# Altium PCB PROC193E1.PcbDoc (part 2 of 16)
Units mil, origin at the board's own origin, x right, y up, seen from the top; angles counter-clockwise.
Board outline 7700 x 2300 mil, 6 copper layers (Top Layer, GND 1, SIG 1, PWR, GND 2, Bottom Layer), stack 60.98 mil thick; 946 components, 667 nets, 9401 pads, 1730 vias.
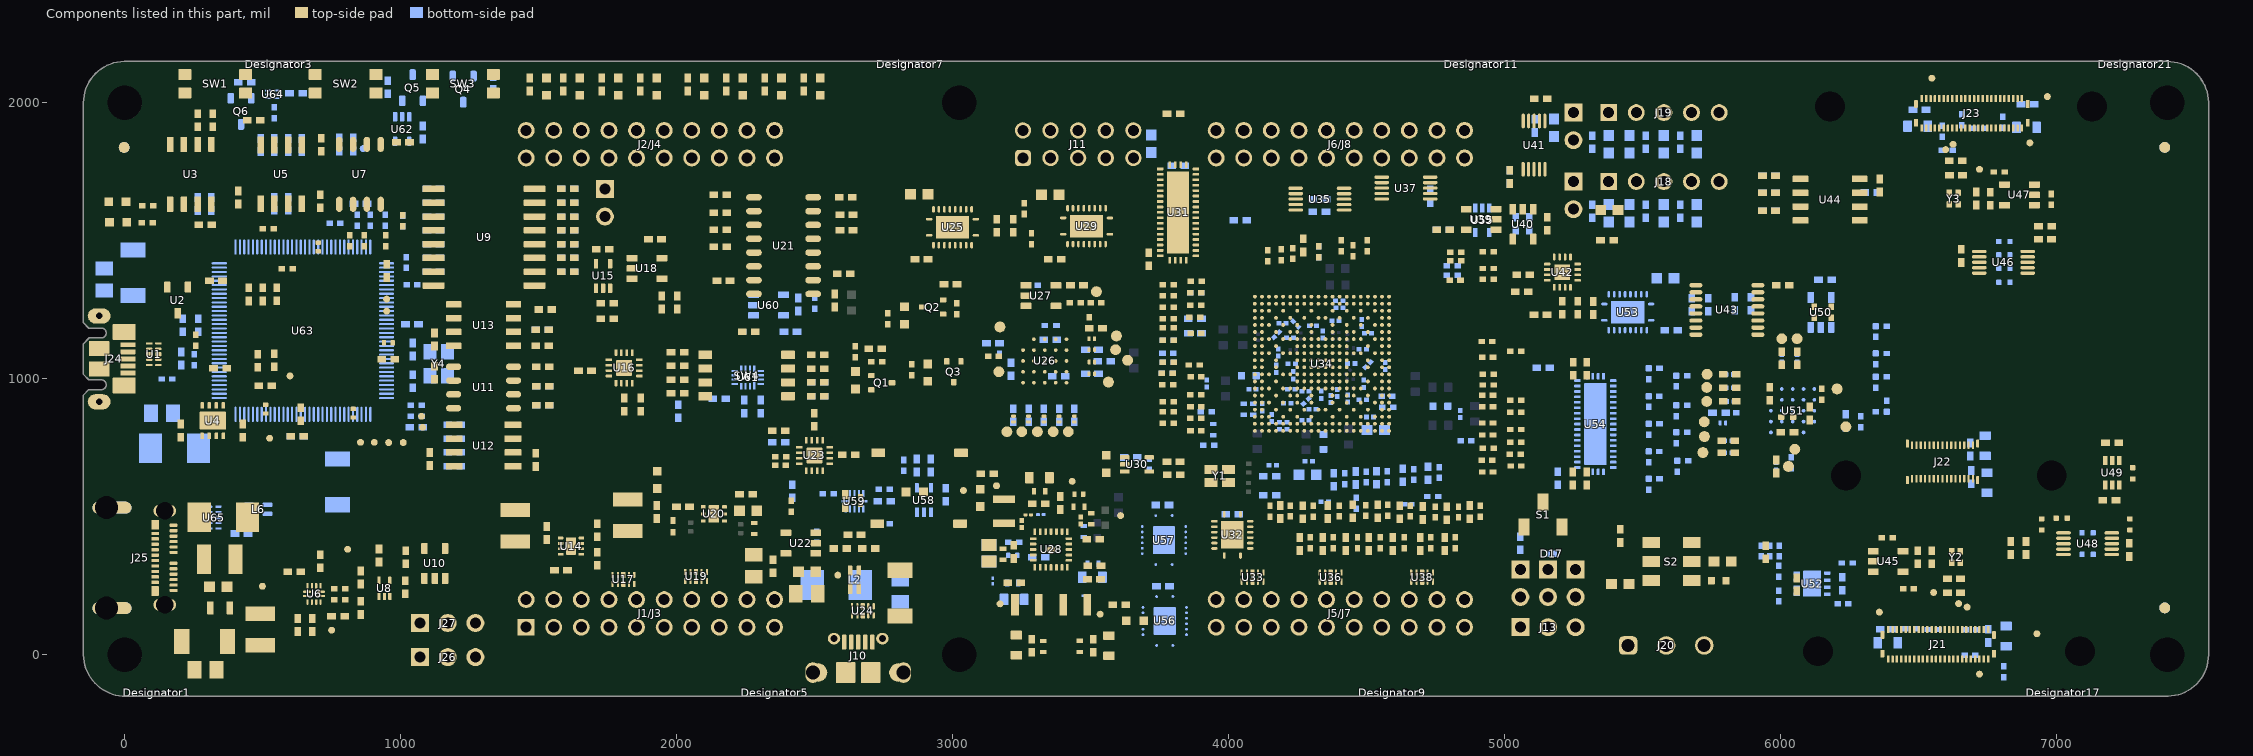
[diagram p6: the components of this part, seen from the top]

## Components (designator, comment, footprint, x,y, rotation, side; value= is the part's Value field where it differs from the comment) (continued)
C247 "885012105010" 0402 3352.74,1142.22 r180 bottom value=0.1uF
C248 "KGM05CR51A106MH" FP-KGM05CR51A106MH_0402-MFG 3354.07,1193.17 r180 bottom value=10µF
C249 "CGA2B3X7R1H104M050BB" 0402 3311.63,353.3 r0 bottom value=0.1uF
C250 "GRM155C71A105KE11D" FP-GRM155C71A105KE11D_0402-MFG 3217.22,360.02 r180 bottom value=1µF
C251 "CGA4J3X7S1A106K125AE" FP-CGA4J3X7S1A106K125AE_0805-MFG 3221.88,200.54 r180 bottom
C252 "GCM155C71A105KE38D" 0402_070 3217.08,260.33 r180 bottom value=1uF
C253 "885012105010" 0402 3210.86,1034.54 r90 bottom value=0.1uF
C254 "CGA4J1X7R1E475K125AC" 0805L 3131.12,367.91 r270 bottom value=4.7uF
C255 "CGA2B3X7R1H104M050BB" 0402 2920.33,686.09 r90 bottom value=0.1uF
C256 "GRM155R71E104KE14D" 0402 2411.77,1170.68 r180 bottom value=0.1uF
C257 "GRM155R71E104KE14D" 0402 2304.62,899.35 r90 bottom value=0.1uF
C258 "GRM155R71E104KE14D" 0402 2244.62,899.35 r90 bottom value=0.1uF
C259 "GRM155R71E104KE14D" 0402 1118.64,1687.95 r0 bottom value=0.1uF
C260 "GRM155R71E104KE14D" 0402 1055.5,824.22 r180 bottom value=0.1uF
C261 "GRM155R71E103KA01D" 0402 1040.5,1197.99 r0 bottom value=0.01uF
C262 "GCM1555C1H8R0DA16D" 0402 1042.72,991.33 r90 bottom
C263 "GCM1555C1H8R0DA16D" 0402 1042.72,1106.13 r270 bottom
C264 "GR442QR73D102KW01L" 1808 770.02,626.55 r270 bottom value=1000pF
C265 "GRM155R71E104KE14D" 0402 624.98,791.85 r180 bottom value=0.1uF
C266 "GRM155R71E104KE14D" 0402 620.64,2034.88 r180 bottom value=0.1uF
C267 "GRM155R71E103KA01D" 0402 265.82,1193.78 r270 bottom value=0.01uF
C268 "GRM155R71E104KE14D" 0402 210.82,1193.78 r270 bottom value=0.1uF
C269 "GRM155R71E103KA01D" 0402 205,1073.49 r270 bottom value=0.01uF
C270 "GRM21BZ71E106KE15L" 0805_HV 135,874.79 r0 bottom value=10uF
C271 "GR442QR73D102KW01L" 1808 30.18,1384.48 r270 bottom value=1000pF
D1 "150060VS75000" WL-SMCW_GREEN -24.03,1567.07 r0 top value=Green
D2 "SMBJ6.5CA" SMB-Bi 357.53,498.6 r180 top value=6.5V
D3 "150060VS75000" WL-SMCW_GREEN 1527.87,2058.31 r90 top value=Green
D4 "150060VS75000" WL-SMCW_GREEN 1647.87,2058.31 r90 top value=Green
D5 "150060VS75000" WL-SMCW_GREEN 1787.87,2058.31 r90 top value=Green
D6 "150060VS75000" WL-SMCW_GREEN 1927.87,2058.31 r90 top value=Green
D7 "150060VS75000" WL-SMCW_GREEN 1929,633.75 r270 top value=Green
D8 "150060VS75000" WL-SMCW_GREEN 2099.29,2058.31 r90 top value=Green
D9 "150060VS75000" WL-SMCW_GREEN 2239.29,2058.31 r90 top value=Green
D10 "150060VS75000" WL-SMCW_GREEN 2379.29,2058.31 r90 top value=Green
D11 "150060VS75000" WL-SMCW_GREEN 2519.29,2058.31 r90 top value=Green
D12 "150060VS75000" WL-SMCW_GREEN 2862.16,590.14 r0 top value=Green
D13 "150060VS75000" WL-SMCW_GREEN 2909.63,1022.06 r270 top value=Green
D14 "150060VS75000" WL-SMCW_GREEN 3099.79,568.86 r90 top value=Green
D15 "150060VS75000" WL-SMCW_GREEN 3555.43,691.04 r90 top value=Green
D16 "150060VS75000" WL-SMCW_GREEN 3660,123 r180 top value=Green
D17 "TPD1E01B04DPYR" DPY0002A 5169.37,365.99 r0 bottom
D18 "SMBJ6.5CA" SMB-Bi 2577.19,253.17 r180 bottom value=6.5V
D19 "SMBJ6.5CA" SMB-Bi 180.09,748.45 r180 bottom value=6.5V
Designator1 "Comment" BRAKE_WAY_HOLES1X3 116.59,-187.57 r0 top
Designator2 "Comment" BRAKE_WAY_HOLES1X3 116.59,2469.63 r0 top
Designator3 "Comment" BRAKE_WAY_HOLES1X3 557.39,2189.63 r180 top
Designator4 "Comment" BRAKE_WAY_HOLES1X3 557.39,4848.63 r180 top
Designator5 "Comment" BRAKE_WAY_HOLES1X3 2354.59,-187.57 r0 top
Designator6 "Comment" BRAKE_WAY_HOLES1X3 2354.59,2469.63 r0 top
Designator7 "Comment" BRAKE_WAY_HOLES1X3 2846.06,2189.63 r180 top
Designator8 "Comment" BRAKE_WAY_HOLES1X3 2846.06,4848.63 r180 top
Designator9 "Comment" BRAKE_WAY_HOLES1X3 4592.59,-187.57 r0 top
Designator10 "Comment" BRAKE_WAY_HOLES1X3 4592.59,2469.63 r0 top
Designator11 "Comment" BRAKE_WAY_HOLES1X3 4914.73,2189.63 r180 top
Designator12 "Comment" BRAKE_WAY_HOLES1X3 4914.73,4848.63 r180 top
Designator13 "Comment" MHNP_M2-5_PANHEAD_PHILLIPS 6134.37,12.93 r0 top
Designator14 "Comment" MHNP_M2-5_PANHEAD_PHILLIPS 6178.06,1987.07 r0 top
Designator15 "Comment" MHNP_M2-5_PANHEAD_PHILLIPS 6235.8,649.92 r270 top
Designator16 "Comment" MHNP_M2-5_PANHEAD_PHILLIPS 6981.47,649.92 r270 top
Designator17 "Comment" BRAKE_WAY_HOLES1X3 7022.59,-187.57 r0 top
Designator18 "Comment" BRAKE_WAY_HOLES1X3 7022.59,2469.63 r0 top
Designator19 "Comment" MHNP_M2-5_PANHEAD_PHILLIPS 7084.37,12.93 r0 top
Designator20 "Comment" MHNP_M2-5_PANHEAD_PHILLIPS 7128.06,1987.07 r0 top
Designator21 "Comment" BRAKE_WAY_HOLES1X3 7283.39,2189.63 r180 top
Designator22 "Comment" BRAKE_WAY_HOLES1X3 7283.39,4848.63 r180 top
DS1 "150060RS75000" WL-SMCW_RED -26.98,1641.17 r0 top value=Red
DS2 "150060RS75000" WL-SMCW_RED 2647.24,994.63 r90 top value=Red
DS3 "150060RS75000" WL-SMCW_RED 2824.74,1229.1 r270 top value=Red
FB1 "BLM18EG121SN1D" FP-BLM18EG121SN1D_0603-MFG 5774.73,268.94 r180 top
FB2 "BLM18EG121SN1D" FP-BLM18EG121SN1D_0603-MFG 4766.77,900.65 r180 bottom
FB3 "BLM18EG121SN1D" FP-BLM18EG121SN1D_0603-MFG 4343.27,771.04 r90 bottom
FB4 "BLM18EG121SN1D" FP-BLM18EG121SN1D_0603-MFG 4072.78,1011.24 r0 bottom
FID1 "Fiducial" Fiducial10-20 -2.36,1838.15 r90 top
FID1_1 "Fiducial" Fiducial10-20 234.16,4992.06 r90 top (schematic designator FID1)
FID1_1_1 "Fiducial" Fiducial10-20 234.16,-327.94 r90 top (schematic designator FID1)
FID1_1_2 "Fiducial" Fiducial10-20 7174.16,-327.94 r270 top (schematic designator FID1)
FID1_1_3 "Fiducial" Fiducial10-20 7174.16,4992.06 r270 top (schematic designator FID1)
FID2 "Fiducial" Fiducial10-20 7391.06,169.73 r90 top
FID3 "Fiducial" Fiducial10-20 7391.06,1838.15 r90 top
FID4 "Fiducial" Fiducial10-20 -2.36,1838.15 r90 bottom
FID4_1 "Fiducial" Fiducial10-20 234.16,4992.06 r90 bottom (schematic designator FID4)
FID4_1_1 "Fiducial" Fiducial10-20 234.16,-327.94 r90 bottom (schematic designator FID4)
FID4_1_2 "Fiducial" Fiducial10-20 7174.16,-327.94 r270 bottom (schematic designator FID4)
FID4_1_3 "Fiducial" Fiducial10-20 7174.16,4992.06 r270 bottom (schematic designator FID4)
FID5 "Fiducial" Fiducial10-20 7391.06,1838.15 r90 bottom
FID6 "Fiducial" Fiducial10-20 7391.06,169.73 r90 bottom
J1/J3 "SSQ-110-03-T-D" BOOSTERPACK_40PIN_J1J3 1904.17,150 r270 bottom locked
J2/J4 "SSQ-110-03-T-D" BoosterPack_40pin_J2J4 1904.17,1850 r270 bottom locked
J5/J7 "SSQ-110-03-T-D" BOOSTERPACK_40PIN_J5J7 4404.17,150 r270 bottom locked
J6/J8 "SSQ-110-03-T-D" BoosterPack_40pin_J6J8 4404.17,1850 r270 bottom locked
J9 "PBC02SAAN" Sullins_PBC02SAAN 1739.61,1637.95 r0 top
J10 "629105150921" FP-629105150921_CONN_PTH_USB_8MM0_5MM6-MFG 2657.27,-45.76 r0 top locked
J11 "PRPC005DAAN-RC" Sullins_xxPC005DAAN-RC 3454.17,1850 r90 top locked
J12 "PBC02SAAN" Sullins_PBC02SAAN 5056.57,259.25 r0 top
J13 "PBC03SAAN" PBC03SAAN 5156.57,100 r0 top locked
J14 "PBC02SAAN" Sullins_PBC02SAAN 5156.57,259.25 r0 top
J15 "PBC02SAAN" Sullins_PBC02SAAN 5248.63,1664.55 r0 top
J16 "PBC02SAAN" Sullins_PBC02SAAN 5248.63,1914.55 r0 top
J17 "PBC02SAAN" Sullins_PBC02SAAN 5256.57,259.25 r0 top
J18 "PEC05SAAN" Sullins_PxC05SAAN 5576.52,1714.55 r0 top locked
J19 "PEC05SAAN" Sullins_PxC05SAAN 5576.52,1964.55 r0 top locked
J20 "OSTTE030161" On-Shore_OSTTE030161 5584.76,33.86 r0 top locked
J21 "DF40GB-48DP-0.4V(58)" FP-DF40GB-48DP-0.4V(58)_HDR48-MFG 6570.16,38.05 r0 top locked
J22 "DF40GB(1.5)-30DS-0.4V(58)" FP-DF40GB(1.5)-30DS-0.4V(58)_HDR30-MFG 6585.89,699.03 r180 top
J23 "DF40GB-48DP-0.4V(58)" FP-DF40GB-48DP-0.4V(58)_HDR48-MFG 6692.31,1961.79 r180 top locked
J24 "1051640001" Molex_1051640001 -150,1072.19 r270 top locked
J25 "2012670005" FP-2012670005_CONN_USB_9MM39_8MM21-MFG 18.56,351.26 r270 top locked
J26 "PBC03SAAN" PBC03SAAN 1170.23,-8.36 r0 top
J27 "PBC03SAAN" PBC03SAAN 1170.23,115.14 r0 top
L1 "BLM21PG300SN1D" FP-BLM21PG300SN1D_0805-MFG 345.42,170.11 r0 top
L2 "DLW21SN900HQ2L" IND_DLW21S 2643.9,271.94 r180 top
L3 "TFM252012ALMA1R5MTAA" TFM252012 3185.47,519.88 r90 top value=1.5uH
L4 "TFM252012ALMA1R0MTAA" TFM252012 3268.77,181.64 r180 top value=1uH
L5 "TFM252012ALMA1R0MTAA" TFM252012 3443.14,181.64 r0 top value=1uH
L6 "DLW21SN900HQ2L" IND_DLW21S 483.07,527.37 r270 bottom
LBL1 "THT-14-423-10" Label_650x200 6955.91,925.96 r0 top
Logo1 "CE Mark" CE_Mark_5mm 770.02,1236.06 r0 top
Logo2 "Texas Instruments" TI_Stacked_Overlay_Small 6780.15,1256.77 r0 top
Logo3 "FCC disclaimer" FCC_disclaimer 9656.36,4210 r270 bottom
Logo4 "WEEE logo" WEEE_Minimum 5570,380 r180 bottom
Q1 "BSS223PWH6327" SOT-323 2742.33,985.75 r0 top value=-20V
Q2 "BSS123W-7-F" SOT-323 2927.29,1259.99 r180 top value=100V
Q3 "BSS223PWH6327" SOT-323 3003.55,1025.48 r270 top value=-20V
Q4 "IRLML6401TRPBF" SOT-23 1226.13,2049.5 r270 bottom value=-12V
Q5 "IRLML6401TRPBF" SOT-23 1042.72,2054.8 r90 bottom value=-12V
Q6 "IRLML6401TRPBF" SOT-23 421.14,1969 r270 bottom value=-12V
R1 "ERJ-2GEJ361X" 0402L 80.97,1565.68 r0 top value=360
R2 "ERJ-2GEJ361X" 0402L 83.02,1626.75 r0 top value=360
R3 "ERJ-6GEY0R00V" 0805_HV 292.01,-54.8 r0 top value=0
R4 "CRCW040233R2FKED" 0402 264.01,1936.89 r270 top value=33.2
R5 "CRCW04021K00FKED" 0402L 257.13,1139.87 r270 top value=1.00k
R6 "CRCW040233R2FKED" 0402 448.79,1305.74 r90 top value=33.2
R7 "CRCW040251K1FKED" 0402 481.97,1065.23 r90 top value=51.1k
R8 "CRCW040233R2FKED" 0402 500,1305.74 r90 top value=33.2
R9 "CRCW04021K00FKED" 0402L 519.68,1543.19 r180 top value=1.00k
R10 "CRCW040230K0FKED" 0402 541.97,1067.17 r270 top value=30.0k
R11 "CRCW040233R2FKED" 0402 549.89,1306.36 r90 top value=33.2
R12 "CRCW04021K00FKED" 0402L 589.15,1399.46 r0 top value=1.00k
R13 "CRCW04024K70JNED" 0402 627.02,108.07 r90 top value=4.7k
R14 "CRCW0402909KFKED" 0402 679.97,108.24 r270 top value=909k
R15 "ERJ-2GEJ102X" 0402 708.66,339.01 r270 top value=1.0k
R16 "CRCW0402200KJNED" 0402 772.87,139.29 r0 top value=200k
R17 "ERJ-2GE0R00X" 0402L 778.19,199.9 r0 top value=0
R18 "ERJ-2GE0R00X" 0402L 778.19,240.01 r0 top value=0
R19 "CRCW04021K00FKED" 0402L 815,1500 r270 top value=1.00k
R20 "ERJ-2RKF1002X" 0402 855.31,169.9 r90 top value=10.0k
R21 "ERJ-2RKF1002X" 0402 855.31,280.29 r270 top value=10.0k
R22 "CRCW04021K00FKED" 0402L 866.99,1500 r270 top value=1.00k
R23 "CRCW04021K00FKED" 0402L 945.89,1500 r270 top value=1.00k
R24 "CRCW04021K00FKED" 0402L 1007.5,1572.5 r90 top value=1.00k
R25 "ERJ-2RKF1002X" 0402 1016.9,245.15 r270 top value=10.0k
R26 "ERJ-2RKF2200X" 0402 1467.87,2066.18 r270 top value=220
R27 "CRCW040233R2FKED" 0402 1512.87,1177.74 r180 top value=33.2
R28 "CRCW040233R2FKED" 0402 1514.02,904.65 r180 top value=33.2
R29 "CRCW040233R2FKED" 0402 1514.02,973.08 r180 top value=33.2
R30 "ERJ-2RKF1002X" 0402 1523.66,1251.09 r180 top value=10.0k
R31 "ERJ-2RKF1002X" 0402 1580.22,305.62 r0 top value=10.0k
R32 "ERJ-2GE0R00X" 0402 1604.79,1387.95 r0 top value=0
R33 "ERJ-2GE0R00X" 0402 1604.79,1437.95 r0 top value=0
R34 "ERJ-2GE0R00X" 0402 1604.79,1487.95 r0 top value=0
R35 "ERJ-2GE0R00X" 0402 1604.79,1537.95 r0 top value=0
R36 "ERJ-2GE0R00X" 0402 1604.79,1587.95 r0 top value=0
R37 "ERJ-2GE0R00X" 0402 1604.79,1637.95 r0 top value=0
R38 "ERJ-2RKF2200X" 0402 1587.87,2066.18 r270 top value=220
R39 "ERJ-2RKF1002X" 0402 1667.16,1029.69 r0 top value=10.0k
R40 "ERJ-2RKF49R9X" 0402 1747.95,1218.35 r180 top value=49.9
R41 "ERJ-2RKF2200X" 0402 1727.87,2066.18 r270 top value=220
R42 "ERJ-2RKF2200X" 0402 1867.87,2066.18 r270 top value=220
R43 "ERJ-2RKF1002X" 0402 1869.25,906.48 r90 top value=10.0k
R44 "ERJ-2RKF5100X" 0402 1927.95,517.31 r270 top value=510
R45 "ERJ-2GE0R00X" 0402 1946.1,1276.61 r270 top value=0
R46 "ERJ-2RKF1002X" 0402 2002.86,946.88 r0 top value=10.0k
R47 "ERJ-2RKF1002X" 0402 2002.86,996.88 r0 top value=10.0k
R48 "ERJ-2RKF1002X" 0402 2002.86,1046.88 r0 top value=10.0k
R49 "ERJ-2RKF1002X" 0402 2002.86,1096.88 r0 top value=10.0k
R50 "ERJ-2RKF1002X" 0402 2022.33,536.03 r0 top value=10.0k
R51 "ERJ-2RKF1002X" 0402 2001.1,1276.61 r90 top value=10.0k
R52 "ERJ-2RKF2200X" 0402 2039.29,2066.18 r270 top value=220
R53 "ERJ-2RKF1002X" 0402 2157.77,1478.99 r0 top value=10.0k
R54 "ERJ-2RKF1002X" 0402 2157.77,1539.3 r0 top value=10.0k
R55 "ERJ-2RKF1002X" 0402 2157.77,1602.28 r0 top value=10.0k
R56 "ERJ-2RKF1002X" 0402 2157.77,1666.96 r0 top value=10.0k
R57 "CRCW04024K70JNED" 0402 2169.34,1355.79 r180 top value=4.7k
R58 "ERJ-2RKF2200X" 0402 2179.29,2066.18 r270 top value=220
R59 "RC0603FR-073K16L" 0603 2258.11,521.35 r0 top value=3.16k
R60 "CRCW04021K50FKED" 0402 2251.01,582.06 r180 top value=1.50k
R61 "ERJ-2RKF1002X" 0402 2260.56,1170.68 r180 top value=10.0k
R62 "ERJ-2RKF2200X" 0402 2319.29,2066.18 r270 top value=220
R63 "ERJ-2RKF1002X" 0402 2369.04,811.04 r180 top value=10.0k
R64 "ERJ-2GE0R00X" 0402L 2375.82,686.11 r180 top value=0
R65 "ERJ-2GE0R00X" 0402L 2376.82,717.8 r180 top value=0
R66 "CRCW040210K0FKED" 0402L 2415.21,537.6 r90 top value=10.0k
R67 "ERJ-2RKF2200X" 0402 2459.29,2066.18 r270 top value=220
R68 "ERJ-2GEJ102X" 0402 2510.93,936.88 r180 top value=1.0k
R69 "ERJ-2GEJ102X" 0402 2510.93,986.88 r180 top value=1.0k
R70 "ERJ-2GEJ102X" 0402 2510.93,1036.88 r180 top value=1.0k
R71 "ERJ-2GEJ102X" 0402 2510.93,1086.88 r180 top value=1.0k
R72 "ERJ-2GE0R00X" 0402 2592.39,385.11 r180 top value=0
R73 "CRCW04024K70JNED" 0402 2604.44,1381.36 r0 top value=4.7k
R74 "ERJ-2GEJ102X" 0402 2611.84,1657.42 r180 top value=1.0k
R75 "ERJ-2RKF1002X" 0402 2614.84,1538.98 r180 top value=10.0k
R76 "ERJ-2RKF1002X" 0402 2614.84,1593.98 r180 top value=10.0k
R77 "ERJ-2RKF1002X" 0402 2623.14,724.27 r180 top value=10.0k
R78 "ERJ-2GE0R00X" 0402 2644.11,434.51 r0 top value=0
R79 "ERJ-2GEJ361X" 0402L 2647.24,1097.96 r90 top value=360
R80 "ERJ-2GE0R00X" 0402 2695.23,385.11 r0 top value=0
R81 "ERJ-2RKF1002X" 0402 2719.28,1108.27 r180 top value=10.0k
R82 "ERJ-2GEJ511X" 0402L 2725.02,1061.57 r180 top value=510
R83 "ERJ-2GEJ361X" 0402L 2763.68,1217.89 r90 top value=360
R84 "ERJ-2GEJ361X" 0402L 2851.59,1032.67 r90 top value=360
R85 "ERJ-2GEJ102X" 0402 2991.89,1342.04 r0 top value=1.0k
R86 "ERJ-2GEJ511X" 0402L 3014.94,1254.13 r270 top value=510
R87 "CRCW0402130RFKED" 0402 3124.79,656.33 r0 top value=130
R88 "ERJ-2RKF1003X" 0402 3145.54,1129.49 r0 bottom value=100k
R89 "CRCW040210K0FKED" 0402L 3147.3,1081.34 r0 top value=10.0k
R90 "ERJ-2RKF1002X" 0402 3160.08,1554.67 r90 top value=10.0k
R91 "ERJ-2RKF1002X" 0402 3219.24,1554.67 r270 top value=10.0k
R92 "CRCW020122R0FNED" "FP-CRCW020122R0FNED_0201 (0603 metric)-MFG" 3219.74,854.33 r90 top locked
R93 "ERJ-2GE0R00X" 0402L 3258.14,1616.81 r90 top value=0
R94 "RC0201JR-070RL" "FP-RC0201JR-070RL_0201 (0603 Metric)-IPC_C" 3273.34,506.89 r180 top
R95 "CRCW020122R0FNED" "FP-CRCW020122R0FNED_0201 (0603 metric)-MFG" 3274.55,854.33 r90 top locked
R96 "ERJ-2GE0R00X" 0402L 3285.03,1507.75 r270 top value=0
R97 "CRCW020122R0FNED" "FP-CRCW020122R0FNED_0201 (0603 metric)-MFG" 3330.3,854.33 r90 top locked
R98 "CRCW020122R0FNED" "FP-CRCW020122R0FNED_0201 (0603 metric)-MFG" 3384.85,854.33 r90 top locked
R99 "CRCW040210K0FKED" 0402L 3443.15,1274.81 r0 top value=10.0k
R100 "CRCW020122R0FNED" "FP-CRCW020122R0FNED_0201 (0603 metric)-MFG" 3440.45,854.33 r90 top locked
R101 "ERJ-2GEJ102X" 0402 3518.48,1183.71 r180 top value=1.0k
R102 "CRCW040210K0FKED" 0402L 3518.96,1275.27 r0 top value=10.0k
R103 "CRCW020122R0FNED" "FP-CRCW020122R0FNED_0201 (0603 metric)-MFG" 3504.13,1105.45 r180 top locked
R104 "CRCW020122R0FNED" "FP-CRCW020122R0FNED_0201 (0603 metric)-MFG" 3504.13,1017.79 r180 top locked
R105 "CRCW020122R0FNED" "FP-CRCW020122R0FNED_0201 (0603 metric)-MFG" 3504.13,1060.79 r180 top locked
R106 "CRCW020122R0FNED" "FP-CRCW020122R0FNED_0201 (0603 metric)-MFG" 3504.13,1145.11 r180 top locked
R107 "CRCW0402130RFKED" 0402 3603.17,180.47 r180 top value=130
R108 "ERJ-2GE0R00X" 0402L 3777.53,1020.3 r0 top value=0
R109 "ERJ-2GE0R00X" 0402L 3779.07,979.21 r0 top locked value=0
R110 "ERJ-2GE0R00X" 0402L 3780.41,881.27 r0 top locked value=0
R111 "ERJ-2GE0R00X" 0402L 3780.41,1140.12 r0 top value=0
R112 "ERJ-2GE0R00X" 0402L 3780.41,1258.93 r0 top value=0
R113 "ERJ-2GE0R00X" 0402L 3780.41,1340.06 r0 top value=0
R114 "ERJ-2GE0R00X" 0402L 3780.52,916.94 r0 top locked value=0
R115 "ERJ-2GE0R00X" 0402L 3780.52,1060.1 r0 top value=0
R116 "ERJ-2GE0R00X" 0402L 3780.52,1300.55 r0 top value=0
R117 "ERJ-2GE0R00X" 0402L 3780.55,1184.33 r0 top value=0
R118 "ERJ-2GE0R00X" 0402L 3780.79,1217.23 r0 top value=0
R119 "ERJ-2GE0R00X" 0402L 3781.1,839.37 r0 top value=0
R120 "ERJ-2RKF1002X" 0402 3800,1960.93 r180 top value=10.0k
R121 "CRCW040210K7FKED" 0402 3800.6,653.2 r180 top value=10.7k
R122 "ERJ-2GE0R00X" 0402L 3874.65,1050.05 r0 top locked value=0
R123 "ERJ-2GE0R00X" 0402L 3877.21,1223.03 r0 top value=0
R124 "ERJ-2GE0R00X" 0402L 3879.86,1311.59 r0 top value=0
R125 "ERJ-2GE0R00X" 0402L 3880.17,856.62 r0 top locked value=0
R126 "ERJ-2GE0R00X" 0402L 3880.17,941.56 r0 top locked value=0
R127 "ERJ-2GE0R00X" 0402L 3880.17,1266.96 r0 top value=0
R128 "ERJ-2GE0R00X" 0402L 3880.89,811.26 r0 top value=0
R129 "ERJ-2GE0R00X" 0402L 3880.89,898.73 r0 top locked value=0
R130 "ERJ-2GE0R00X" 0402L 3881.03,1007.37 r0 top locked value=0
R131 "ERJ-2GE0R00X" 0402L 3881.03,1164.73 r0 top value=0
R132 "ERJ-2GE0R00X" 0402L 3882.07,1353.51 r0 top value=0
R133 "ERJ-2GE0R00X" 0402L 4140.45,1445.55 r270 top value=0
R134 "ERJ-2GE0R00X" 0402L 4149.38,520.42 r90 top value=0
R135 "ERJ-2RKF33R0X" 0402L 4190.71,1449.35 r270 top value=33.0
R136 "ERJ-2GE0R00X" 0402L 4223.28,520.93 r90 top value=0
R137 "ERJ-2RKF33R0X" 0402L 4231.93,1453.95 r270 top value=33.0
R138 "CRCW040233R2FKED" 0402 4269.11,1483.33 r270 top value=33.2
R139 "ERJ-2GE0R00X" 0402L 4295.85,405.37 r90 top value=0
R140 "ERJ-2GE0R00X" 0402L 4305.78,520.7 r90 top value=0
R141 "ERJ-2GE0R00X" 0402L 4325.9,1460.5 r270 top value=0
R142 "ERJ-2GE0R00X" 0402L 4377.79,405.37 r90 top value=0
R143 "ERJ-2GE0R00X" 0402L 4400.37,520.91 r90 top value=0
R144 "ERJ-2GE0R00X" 0402L 4407.89,1482.32 r270 top value=0
R145 "ERJ-2GE0R00X" 0402L 4450.05,1463.81 r270 top value=0
R146 "ERJ-2GE0R00X" 0402L 4466.27,405.37 r90 top value=0
R147 "ERJ-2GE0R00X" 0402L 4496.07,523.01 r90 top value=0
R148 "ERJ-2GE0R00X" 0402L 4502.07,1482.32 r270 top value=0
R149 "ERJ-2GE0R00X" 0402L 4548.85,405.37 r90 top value=0
R150 "ERJ-2GE0R00X" 0402L 4576.34,523.9 r90 top value=0
R151 "ERJ-2GE0R00X" 0402L 4635.29,405.37 r90 top value=0
R152 "ERJ-2GE0R00X" 0402L 4658.15,521.04 r90 top value=0
R153 "ERJ-2GE0R00X" 0402L 4731.21,405.37 r90 top value=0
R154 "ERJ-2GE0R00X" 0402L 4747.35,517.2 r90 top value=0
R155 "ERJ-2GE0R00X" 0402L 4819.82,1357.29 r180 top value=0
R156 "ERJ-2GE0R00X" 0402L 4822.76,1428.43 r180 top value=0
R157 "ERJ-2GE0R00X" 0402L 4822.82,1457.97 r180 top value=0
R158 "ERJ-2GE0R00X" 0402L 4819.72,405.37 r90 top value=0
R159 "ERJ-2GE0R00X" 0402L 4832.2,517.2 r90 top value=0
R160 "ERJ-2GE0R00X" 0402L 4911.17,520.31 r90 top value=0
R161 "ERJ-2GE0R00X" 0402L 4935.36,1135.18 r180 top value=0
R162 "ERJ-2GE0R00X" 0402L 4935.36,705.05 r180 top locked value=0
R163 "ERJ-2GE0R00X" 0402L 4937.53,1077.65 r180 top value=0
R164 "ERJ-2GE0R00X" 0402L 4937.53,796.32 r180 top locked value=0
R165 "ERJ-2GE0R00X" 0402L 4937.53,839.92 r180 top locked value=0
R166 "ERJ-2GE0R00X" 0402L 4937.53,898.29 r180 top value=0
R167 "ERJ-2RKF33R0X" 0402L 4937.53,941.07 r180 top value=33.0
R168 "ERJ-2GE0R00X" 0402L 4937.53,662.42 r180 top locked value=0
R169 "ERJ-2GE0R00X" 0402L 4939.87,748.79 r180 top locked value=0
R170 "ERJ-2GE0R00X" 0402L 4939.87,977.47 r180 top value=0
R171 "ERJ-2GE0R00X" 0402L 4940.27,1359.91 r180 top value=0
R172 "ERJ-2GE0R00X" 0402L 4940.27,1460.66 r180 top value=0
R173 "ERJ-2GE0R00X" 0402L 4940.5,1399.64 r180 top value=0
R174 "ERJ-2GE0R00X" 0402L 4940.5,1015.72 r180 top value=0
R175 "ERJ-2RKF1002X" 0402 5017.69,1731.43 r270 top value=10.0k
R176 "ERJ-2GE0R00X" 0402L 5037.64,726.94 r180 top locked value=0
R177 "ERJ-2GE0R00X" 0402L 5040,770 r180 top locked value=0
R178 "ERJ-2GE0R00X" 0402L 5040.17,816.26 r180 top locked value=0
R179 "ERJ-2GE0R00X" 0402L 5040.17,878.37 r180 top locked value=0
R180 "ERJ-2RKF33R0X" 0402L 5040.17,922.71 r180 top value=33.0
R181 "ERJ-2GE0R00X" 0402L 5040.17,1100.6 r180 top value=0
R182 "ERJ-2GE0R00X" 0402L 5040.47,684.02 r180 top locked value=0
R183 "CRCW04024K70JNED" 0402 5061.24,1315.92 r180 top value=4.7k
R184 "ERJ-2RKF1002X" 0402 5067.22,1376.37 r0 top value=10.0k
R185 "CRCW04024K70JNED" 0402 5129.12,1231.83 r0 top value=4.7k
R186 "ERJ-2RKF1002X" 0402 5246.75,638.83 r90 top value=10.0k
R187 "ERJ-2RKF1002X" 0402 5247.81,1036.59 r270 top value=10.0k
R188 "ERJ-2RKF1002X" 0402 5263.64,1257.86 r90 top value=10.0k
R189 "ERJ-2RKF1002X" 0402 5297.29,638.83 r270 top value=10.0k
R190 "ERJ-2RKF1002X" 0402 5297.67,1036.59 r90 top value=10.0k
R191 "ERJ-2RKF1002X" 0402 5321.3,1256.72 r90 top value=10.0k
R192 "ERJ-2RKF4992X" 0402 5370.69,1501.35 r0 top value=49.9k
R193 "ERJ-2RKF4992X" 0402 5809.18,731.78 r180 top locked value=49.9k
R194 "ERJ-2RKF4992X" 0402 5809.18,775.07 r180 top locked value=49.9k
R195 "ERJ-2GEJ102X" 0402 5776.42,877.17 r0 bottom value=1.0k
R196 "ERJ-2RKF4992X" 0402 5814.66,1015.72 r180 top value=49.9k
R197 "ERJ-2RKF4992X" 0402 5814.85,967 r180 top locked value=49.9k
R198 "ERJ-2RKF4992X" 0402 5815.44,917.95 r180 top value=49.9k
R199 "CRCW040210K0FKED" 0402L 5819.73,877.17 r0 bottom value=10.0k
R200 "ERJ-2RKF1002X" 0402 5957.45,1736.2 r0 top value=10.0k
R201 "ERJ-2RKF1002X" 0402 5957.45,1609.41 r0 top value=10.0k
R202 "ERJ-2RKF1002X" 0402 5957.45,1674.05 r0 top value=10.0k
R203 "ERJ-2RKF4992X" 0402 5982.95,682.4 r270 top locked value=49.9k
R204 "ERJ-2RKF4992X" 0402 6003.63,1074.31 r90 top value=49.9k
R205 "CRCW04024K70JNED" 0402 6058.96,1074.31 r270 top value=4.7k
R206 "CRCW040210K0FKED" 0402L 6121.79,1240.64 r270 top value=10.0k
R207 "CRCW040210K0FKED" 0402L 6148.3,943.74 r270 top value=10.0k
R208 "CRCW040210K0FKED" 0402L 6182.93,1240.64 r90 top value=10.0k
R209 "CRCW040210K0FKED" 0402L 6385.94,424 r0 top value=10.0k
R210 "CRCW040210K0FKED" 0402L 6462.69,239.5 r0 top value=10.0k
R211 "ERJ-2GE0R00X" 0402 6627.47,275.05 r180 top value=0
R212 "ERJ-2GE0R00X" 0402 6627.69,224.48 r180 top value=0
R213 "ERJ-2GE0R00X" 0402 6634.2,1790.07 r0 top value=0
R214 "ERJ-2GE0R00X" 0402 6634.56,1736.89 r0 top value=0
R215 "CRCW040210K0FKED" 0402L 6790.91,1749.22 r180 top value=10.0k
R216 "ERJ-2RKF1002X" 0402 6833.24,387.01 r90 top value=10.0k
R217 "ERJ-2RKF1002X" 0402 6888.43,387.01 r270 top value=10.0k
R218 "ERJ-2RKF1002X" 0402 6957.26,1504.96 r0 top value=10.0k
R219 "ERJ-2RKF1002X" 0402 6957.65,1553.28 r180 top value=10.0k
R220 "ERJ-2GEJ152X" FP-ERJ-2GEJ152X_0402-MFG 6945.06,472.45 r90 top value=1.5k
R221 "CRCW040210K0FKED" 0402L 6980.08,1649.85 r90 top value=10.0k
R222 "ERJ-2GEJ152X" FP-ERJ-2GEJ152X_0402-MFG 7017.89,495.49 r0 top value=1.5k
R223 "ERJ-2GEJ152X" FP-ERJ-2GEJ152X_0402-MFG 7265.02,472.45 r90 top value=1.5k
R224 "ERJ-2GEJ152X" FP-ERJ-2GEJ152X_0402-MFG 7275.03,657.64 r90 top value=1.5k
R225 "ERJ-2GEJ152X" FP-ERJ-2GEJ152X_0402-MFG 7111.74,363.62 r180 bottom value=1.5k
R226 "ERJ-2GEJ152X" FP-ERJ-2GEJ152X_0402-MFG 7111.74,442.03 r180 bottom value=1.5k
R227 "ERJ-2GEJ152X" FP-ERJ-2GEJ152X_0402-MFG 6810.02,1349.46 r0 bottom value=1.5k
R228 "ERJ-2GEJ152X" FP-ERJ-2GEJ152X_0402-MFG 6810.02,1448.74 r0 bottom value=1.5k
R229 "ERJ-2GEJ152X" FP-ERJ-2GEJ152X_0402-MFG 6810.02,1497.54 r0 bottom value=1.5k
R230 "ERJ-2GEJ152X" FP-ERJ-2GEJ152X_0402-MFG 6810.02,1400.32 r0 bottom value=1.5k
R231 "CRCW040210K0FKED" 0402L 6807.81,-61.16 r90 bottom value=10.0k
R232 "CRCW040210K0FKED" 0402L 6804.23,1929.98 r90 bottom value=10.0k
R233 "CRCW040210K0FKED" 0402L 6717.17,1908.33 r180 bottom value=10.0k
R234 "CRCW040210K0FKED" 0402L 6688.86,90.62 r0 bottom value=10.0k
R235 "CRCW040210K0FKED" 0402L 6685.69,-2.31 r0 bottom value=10.0k
R236 "CRCW040210K0FKED" 0402L 6655.79,1938.86 r270 bottom value=10.0k
R237 "CRCW040210K0FKED" 0402L 6602.65,1828.78 r180 bottom value=10.0k
R238 "CRCW040210K0FKED" 0402L 6585.42,1897.4 r90 bottom value=10.0k
R239 "CRCW040210K0FKED" 0402L 6552.37,91.67 r0 bottom value=10.0k
R240 "CRCW040210K0FKED" 0402L 6470.83,94.86 r0 bottom value=10.0k
R241 "ERJ-2GE0R00X" 0402L 6364.21,1191.18 r0 bottom value=0
R242 "ERJ-2GE0R00X" 0402L 6363.73,880.32 r180 bottom locked value=0
R243 "ERJ-2GE0R00X" 0402L 6363.4,1007.26 r0 bottom locked value=0
R244 "ERJ-2GE0R00X" 0402L 6363.4,1091.76 r0 bottom value=0
R245 "ERJ-2GE0R00X" 0402L 6383.42,900.01 r90 bottom locked value=0
R246 "ERJ-2RKF1002X" 0402 6328.27,1675 r0 bottom value=10.0k
R247 "ERJ-2GE0R00X" 0402L 6344.52,1171.49 r270 bottom value=0
R248 "ERJ-2GE0R00X" 0402L 6343.71,987.57 r270 bottom locked value=0
R249 "ERJ-2GE0R00X" 0402L 6343.71,1072.07 r270 bottom value=0
R250 "CRCW040210K0FKED" 0402L 6290.18,843.92 r90 bottom value=10.0k
R251 "ERJ-2GE0R00X" 0402L 6240.31,332.71 r180 bottom value=0
R252 "ERJ-2GE0R00X" 0402L 6225.31,185.71 r180 bottom value=0
R253 "ERJ-2RKF1003X" 0402 6235.99,847.9 r270 bottom value=100k
R254 "CRCW020122R0FNED" "FP-CRCW020122R0FNED_0201 (0603 metric)-MFG" 6058.96,1074.31 r270 bottom locked
R255 "CRCW040210K0FKED" 0402L 6037.35,695.34 r90 bottom value=10.0k
R256 "CRCW020122R0FNED" "FP-CRCW020122R0FNED_0201 (0603 metric)-MFG" 6003.63,1074.31 r270 bottom locked
R257 "CRCW040210K0FKED" 0402L 5994.28,375.96 r90 bottom value=10.0k
R258 "ERJ-2RKF1002X" 0402 5957.45,1609.41 r0 bottom value=10.0k
R259 "ERJ-2RKF1002X" 0402 5957.45,1674.05 r0 bottom value=10.0k
R260 "ERJ-2RKF1002X" 0402 5957.45,1736.2 r0 bottom value=10.0k
R261 "CRCW040261R9FKED" 0402L 5993.11,213.03 r90 bottom value=61.9
R262 "CRCW040261R9FKED" 0402L 5993.11,302.4 r270 bottom value=61.9
R263 "CRCW020122R0FNED" "FP-CRCW020122R0FNED_0201 (0603 metric)-MFG" 5982.95,682.4 r90 bottom
R264 "CRCW040210K0FKED" 0402L 5960.46,375.96 r270 bottom value=10.0k
R265 "ERJ-2GE0R00X" 0402L 5928.76,375.96 r90 bottom value=0
R266 "ERJ-2RKF1002X" 0402 5892.01,1272.13 r90 bottom value=10.0k
R267 "ERJ-2RKF1002X" 0402 5833.71,1272.13 r270 bottom value=10.0k
R268 "CRCW020122R0FNED" "FP-CRCW020122R0FNED_0201 (0603 metric)-MFG" 5817.61,917.95 r0 bottom locked
R269 "CRCW020122R0FNED" "FP-CRCW020122R0FNED_0201 (0603 metric)-MFG" 5814.85,967 r0 bottom
R270 "CRCW020122R0FNED" "FP-CRCW020122R0FNED_0201 (0603 metric)-MFG" 5814.66,1015.72 r0 bottom locked
R271 "CRCW020122R0FNED" "FP-CRCW020122R0FNED_0201 (0603 metric)-MFG" 5809.18,731.78 r0 bottom
R272 "CRCW020122R0FNED" "FP-CRCW020122R0FNED_0201 (0603 metric)-MFG" 5809.18,775.07 r0 bottom locked
R273 "CRCW020122R0FNED" "FP-CRCW020122R0FNED_0201 (0603 metric)-MFG" 5789.96,840 r0 bottom
R274 "ERJ-2RKF1002X" 0402 5737.89,1268.2 r270 bottom value=10.0k
R275 "ERJ-2RKF1002X" 0402 5676.49,1268.2 r90 bottom value=10.0k
R276 "ERJ-2GE0R00X" 0402L 5644.89,702.58 r0 bottom locked value=0
R277 "ERJ-2GE0R00X" 0402L 5640.96,805.69 r0 bottom locked value=0
R278 "ERJ-2GE0R00X" 0402L 5640.96,903.91 r0 bottom locked value=0
R279 "ERJ-2GE0R00X" 0402L 5640.96,1011.62 r0 bottom locked value=0
R280 "ERJ-2RKF4992X" 0402 5635.69,1607.42 r270 bottom value=49.9k
R281 "ERJ-2RKF4992X" 0402 5635.69,1857.42 r270 bottom value=49.9k
R282 "ERJ-2GE0R00X" 0402L 5625.21,682.89 r270 bottom locked value=0
R283 "ERJ-2GE0R00X" 0402L 5621.27,786 r270 bottom locked value=0
R284 "ERJ-2GE0R00X" 0402L 5621.27,884.22 r270 bottom locked value=0
R285 "ERJ-2GE0R00X" 0402L 5621.27,991.94 r270 bottom locked value=0
R286 "ERJ-2GE0R00X" 0402L 5540.83,638.11 r0 bottom locked value=0
R287 "ERJ-2GE0R00X" 0402L 5540.83,837.39 r0 bottom locked value=0
R288 "ERJ-2GE0R00X" 0402L 5540.83,1038.57 r0 bottom locked value=0
R289 "ERJ-2GE0R00X" 0402L 5540.65,736.65 r0 bottom value=0
R290 "ERJ-2GE0R00X" 0402L 5540.65,937.41 r0 bottom locked value=0
R291 "ERJ-2GE0R00X" 0402L 5521.14,618.42 r270 bottom locked value=0
R292 "ERJ-2GE0R00X" 0402L 5521.14,817.71 r270 bottom locked value=0
R293 "ERJ-2GE0R00X" 0402L 5521.14,1018.89 r270 bottom locked value=0
R294 "ERJ-2GE0R00X" 0402L 5520.97,716.97 r270 bottom locked value=0
R295 "ERJ-2GE0R00X" 0402L 5520.97,917.72 r270 bottom locked value=0
R296 "ERJ-2RKF4992X" 0402 5511.52,1607.42 r270 bottom value=49.9k
R297 "ERJ-2RKF4992X" 0402 5511.52,1857.42 r270 bottom value=49.9k
R298 "ERJ-2RKF4992X" 0402 5316.52,1607.42 r270 bottom value=49.9k
R299 "ERJ-2RKF4992X" 0402 5316.52,1857.42 r270 bottom value=49.9k
R300 "ERJ-2RKF4992X" 0402 5107.66,1916.28 r270 bottom value=49.9k
R301 "ERJ-2RKF1002X" 0402 5088.74,1561.7 r90 bottom value=10.0k
R302 "ERJ-2RKF1002X" 0402 5039.74,1561.7 r270 bottom value=10.0k
R303 "ERJ-2RKF1002X" 0402 5017.69,1731.43 r90 bottom value=10.0k
R304 "ERJ-2GE0R00X" 0402L 4859.53,775.15 r180 bottom value=0
R305 "ERJ-2GE0R00X" 0402L 4810.08,1374.48 r180 bottom value=0
R306 "ERJ-2GE0R00X" 0402L 4810.08,1409.48 r180 bottom value=0
R307 "ERJ-2GE0R00X" 0402L 4762.73,660.33 r90 bottom value=0
R308 "ERJ-2GE0R00X" 0402L 4738.35,573.48 r180 bottom value=0
R309 "ERJ-2GE0R00X" 0402L 4669.52,653.06 r90 bottom value=0
R310 "ERJ-2RKF33R0X" 0402L 4575.75,897.39 r180 bottom value=33.0
R311 "ERJ-2RKF33R0X" 0402L 4573.38,937.13 r180 bottom value=33.0
R312 "ERJ-2GE0R00X" 0402L 4573.38,644.6 r90 bottom value=0
R313 "ERJ-2GE0R00X" 0402L 4498.12,644.34 r90 bottom value=0
R314 "ERJ-2GE0R00X" 0402L 4461.48,549.6 r270 bottom value=0
R315 "ERJ-2GE0R00X" 0402L 4419.55,637.93 r90 bottom value=0
R316 "ERJ-2RKF1002X" 0402 4328.29,1604.76 r0 bottom value=10.0k
R317 "ERJ-2GE0R00X" 0402L 4325.9,1460.5 r270 bottom value=0
R318 "ERJ-2RKF1002X" 0402 4148.72,577.42 r180 bottom value=10.0k
R319 "CRCW04022K67FKED" 0402 4148.72,647.28 r0 bottom value=2.67k
R320 "ERJ-2GE0R00X" 0402S 4089.02,889.83 r270 bottom value=0
R321 "ERJ-2GE0R00X" 0402S 4053.85,889.83 r270 bottom value=0
R322 "CRCW040210K0FKED" 0402L 3927.37,759.53 r180 bottom value=10.0k
R323 "ERJ-2GE0R00X" 0402S 3943.1,815.59 r90 bottom value=0
R324 "ERJ-2GE0R00X" 0402L 3918.64,880.3 r0 bottom locked value=0
R325 "ERJ-2GE0R00X" 0402 3877.39,1165.28 r180 bottom value=0
R326 "ERJ-2GE0R00X" 0402 3877.21,1217.23 r0 bottom value=0
R327 "ERJ-2GE0R00X" 0402L 3879.73,1311.83 r180 bottom value=0
R328 "ERJ-2RKF1002X" 0402 3816.71,1771.42 r180 bottom value=10.0k
R329 "ERJ-2GE0R00X" 0402L 3780.52,1060.1 r0 bottom locked value=0
R330 "ERJ-2GE0R00X" 0402L 3780.41,1140.12 r0 bottom value=0
R331 "ERJ-2GE0R00X" 0402L 3779.5,1092.98 r0 bottom value=0
R332 "ERJ-2GE0R00X" 0402L 3777.53,1020.3 r0 bottom locked value=0
R333 "CRCW040210K0FKED" 0402L 3711.65,690.93 r270 bottom value=10.0k
R334 "CRCW0402130RFKED" 0402 3644.68,714.83 r0 bottom value=130
R335 "ERJ-2RKF4992X" 0402 3548.77,1063.53 r0 bottom value=49.9k
R336 "ERJ-2RKF4992X" 0402 3504.13,1017.79 r0 bottom value=49.9k
R337 "CRCW04024K70JNED" 0402 3504.13,1105.45 r180 bottom value=4.7k
R338 "RC0201JR-070RL" "FP-RC0201JR-070RL_0201 (0603 Metric)-IPC_C" 3483.96,214.09 r0 bottom
R339 "ERJ-2RKF4992X" 0402 3440.45,867.92 r270 bottom value=49.9k
R340 "CRCW040210K0FKED" 0402L 3494.85,1203.39 r90 top value=10.0k
R341 "ERJ-2RKF4992X" 0402 3384.85,867.92 r270 bottom value=49.9k
R342 "ERJ-2RKF4992X" 0402 3330.3,867.92 r270 bottom value=49.9k
R343 "RC0201JR-070RL" "FP-RC0201JR-070RL_0201 (0603 Metric)-IPC_C" 3319.23,507.77 r180 bottom
R344 "CRCW040210K0FKED" 0402L 3287.95,1338.26 r0 bottom value=10.0k
R345 "ERJ-2RKF4992X" 0402 3274.55,867.92 r270 bottom value=49.9k
R346 "CRCW040210K0FKED" 0402L 3220.65,408.41 r180 bottom value=10.0k
R347 "ERJ-2RKF4992X" 0402 3219.74,867.92 r270 bottom value=49.9k
R348 "CRCW040210K0FKED" 0402L 3169.16,1109.81 r270 bottom value=10.0k
R349 "RC0201JR-070RL" "FP-RC0201JR-070RL_0201 (0603 Metric)-IPC_C" 3144.53,267.24 r270 bottom
R350 "CRCW0402130RFKED" 0402 2974.77,579.97 r90 bottom value=130
R351 "CRCW04025K23FKED" 0402 2870.22,686.09 r270 bottom value=5.23k
R352 "ERJ-6GEY0R00V" 0805_HV 2808.95,232.21 r90 bottom value=0
R353 "CRCW040210K0FKED" 0402L 2821.99,686.09 r270 bottom value=10.0k
R354 "CRCW040216K5FKED" 0402 2751.29,555.71 r0 bottom value=16.5k
R355 "CRCW040210K0FKED" 0402L 2751.29,599.99 r180 bottom value=10.0k
R356 "CRCW040210K0FKED" 0402L 2751.22,474.92 r180 bottom value=10.0k
R357 "CRCW040210K0FKED" 0402L 2548.88,584.08 r0 bottom value=10.0k
R358 "ERJ-2RKF1002X" 0402 2510.93,936.88 r180 bottom value=10.0k
R359 "ERJ-2RKF1002X" 0402 2510.93,986.88 r180 bottom value=10.0k
R360 "CRCW040210K0FKED" 0402L 2506.66,425.53 r90 bottom value=10.0k
R361 "CRCW040210K0FKED" 0402L 2499.12,1273.35 r270 bottom value=10.0k
R362 "ERJ-2RKF1002X" 0402 2440.44,1269.3 r90 bottom value=10.0k
R363 "ERJ-2RKF1002X" 0402 2417.61,592.55 r270 bottom value=10.0k
R364 "ERJ-2RKF1002X" 0402 2369.04,770 r0 bottom value=10.0k
R365 "ERJ-2GE0R00X" 0402L 2260.56,1170.68 r0 bottom value=0
R366 "ERJ-2RKF1002X" 0402 2154.07,927.14 r0 bottom value=10.0k
R367 "ERJ-2GE0R00X" 0402 2005.84,881.97 r270 bottom value=0
R368 "ERJ-2RKF1002X" 0402 1604.79,1387.95 r0 bottom value=10.0k
R369 "ERJ-2RKF1002X" 0402 1604.79,1437.95 r0 bottom value=10.0k
R370 "ERJ-2RKF1002X" 0402 1604.79,1487.95 r0 bottom value=10.0k
R371 "ERJ-2RKF1002X" 0402 1604.79,1537.95 r0 bottom value=10.0k
R372 "ERJ-2RKF1002X" 0402 1604.79,1587.95 r0 bottom value=10.0k
R373 "ERJ-2RKF1002X" 0402 1604.79,1637.95 r0 bottom value=10.0k
R374 "ERJ-2GEJ102X" 0402 1604.79,1687.95 r0 bottom value=1.0k
R375 "ERJ-2RKF1002X" 0402 1514.02,904.65 r0 bottom value=10.0k
R376 "ERJ-2RKF1002X" 0402 1514.02,973.08 r0 bottom value=10.0k
R377 "ERJ-2RKF1002X" 0402 1512.87,1177.74 r0 bottom value=10.0k
R378 "ERJ-2RKF1002X" 0402 1335.24,2071.5 r270 bottom value=10.0k
R379 "CRCW04024K70JNED" 0402 1193.7,683.03 r180 bottom value=4.7k
R380 "ERJ-2GE0R00X" 0402 1193.7,733.03 r0 bottom value=0
R381 "ERJ-2GE0R00X" 0402 1193.7,783.03 r0 bottom value=0
R382 "CRCW04024K70JNED" 0402 1193.7,833.03 r180 bottom value=4.7k
R383 "ERJ-2RKF1002X" 0402 1118.64,1387.95 r0 bottom value=10.0k
R384 "ERJ-2RKF1002X" 0402 1118.64,1437.95 r0 bottom value=10.0k
R385 "ERJ-2RKF1002X" 0402 1118.64,1487.95 r0 bottom value=10.0k
R386 "ERJ-2RKF1002X" 0402 1118.64,1537.95 r0 bottom value=10.0k
R387 "ERJ-2RKF1002X" 0402 1118.64,1587.95 r0 bottom value=10.0k
R388 "ERJ-2RKF1002X" 0402 1118.64,1637.95 r0 bottom value=10.0k
R389 "ERJ-2RKF1002X" 0402 1079.41,1892.59 r90 bottom value=10.0k
R390 "ERJ-2GEJ101X" 0402L 1055.5,864.22 r0 bottom value=100
R391 "ERJ-2GE0R00X" 0402L 1055.5,904.21 r180 bottom value=0
R392 "CRCW040210K0FKED" 0402L 1040.5,1340.39 r0 bottom value=10.0k
R393 "CRCW040249R9FKED" 0402L 1020,1421.25 r90 bottom value=49.9
R394 "CRCW04021K00FKED" 0402L 1007.56,1571.99 r90 bottom value=1.00k
R395 "ERJ-2RKF1002X" 0402 952.36,2056.56 r270 bottom value=10.0k
R396 "CRCW04021K00FKED" 0402L 943.35,1574.68 r90 bottom value=1.00k
R397 "ERJ-2RKF1002X" 0402 853.95,1634.77 r180 bottom value=10.0k
R398 "CRCW04021K00FKED" 0402L 889.13,1574.68 r90 bottom value=1.00k
R399 "CRCW04021K00FKED" 0402L 842.24,1574.68 r90 bottom value=1.00k
R400 "ERJ-2GE0R00X" 0402 827.09,1849.31 r270 bottom value=0
R401 "ERJ-2RKF1002X" 0402 777.09,1849.31 r270 bottom value=10.0k
R402 "CRCW04024K87FKED" 0402L 761.79,1563.62 r0 bottom value=4.87k
R403 "CRCW04024K70JNED" 0402 641.82,1847.11 r90 bottom value=4.7k
R404 "CRCW04024K70JNED" 0402 591.82,1634.52 r90 bottom value=4.7k
R405 "ERJ-2GE0R00X" 0402 591.82,1847.11 r270 bottom value=0
R406 "CRCW04024K70JNED" 0402 541.82,1634.52 r90 bottom value=4.7k
R407 "ERJ-2GE0R00X" 0402 541.82,1847.11 r270 bottom value=0
R408 "ERJ-2GE0R00X" 0402L 541.97,1964.1 r90 bottom value=0
R409 "CRCW04024K70JNED" 0402 491.82,1847.11 r90 bottom value=4.7k
R410 "ERJ-2RKF1002X" 0402 434.4,2074.5 r180 bottom value=10.0k
R411 "ERJ-2RKF1002X" 0402 422.78,439.51 r180 bottom value=10.0k
R412 "ERJ-2GE0R00X" 0402 314.01,1633.24 r270 bottom value=0
R413 "ERJ-2GE0R00X" 0402 264.01,1633.24 r270 bottom value=0
R414 "CRCW0402330KFKED" 0402L 251.47,1069.49 r270 bottom value=330k
R415 "CRCW0402330KFKED" 0402L 152.83,999.2 r180 bottom value=330k
R416 "ERJ-6GEY0R00V" 0805_HV -74.82,1359.48 r90 bottom value=0
S1 "CAS-120TA" SW_CAS-120TA 5138.66,508.21 r90 top
S2 "CAS-D20TA" SW_CAS-D20TA 5603.83,337.83 r180 top
SH-J1 "60900213421" Wurth_60900213421 1700.31,-430 r180 top
SH-J2 "60900213421" Wurth_60900213421 1725,-310 r180 top
SH-J3 "60900213421" Wurth_60900213421 4195,-400 r180 top
SH-J4 "60900213421" Wurth_60900213421 4205,-270 r180 top
SH-J5 "60900213421" Wurth_60900213421 8798.79,1261.89 r90 top
SH-J6 "60900213421" Wurth_60900213421 9028.01,1581.88 r90 top
SH-J7 "60900213421" Wurth_60900213421 9026.52,1267.06 r90 top
SH-J8 "60900213421" Wurth_60900213421 8792.76,1576 r90 top
SW1 "434351045816" FP-434351045816_SMT_SW_4MM7_4MM5-MFG 327.56,2068.82 r180 top
SW2 "434351045816" FP-434351045816_SMT_SW_4MM7_4MM5-MFG 800,2068.82 r180 top locked
SW3 "434351045816" FP-434351045816_SMT_SW_4MM7_4MM5-MFG 1225,2068.82 r180 top locked
SW4 "416131160804" FP-416131160804_SMT_SW-MFG 2253.23,1011.88 r90 top
SW5 "416131160801" FP-416131160801_DIP_SW_1-MFG 2876.22,474.92 r0 top
SW6 "416131160801" FP-416131160801_DIP_SW_1-MFG 2880.02,731.93 r180 top
TP1 "TESTPOINT" TP_25MIL-SMT 498.59,248.33 r180 top
TP2 "TESTPOINT" TP_25MIL-SMT 524.75,784.53 r270 top
TP3 "TESTPOINT" TP_25MIL-SMT 598.48,1010.35 r0 top
TP4 "TESTPOINT" TP_25MIL-SMT 749.46,89.1 r90 top
TP5 "TESTPOINT" TP_25MIL-SMT 807.27,382.27 r90 top
TP6 "TESTPOINT" TP_25MIL-SMT 853.9,770 r270 top
TP7 "TESTPOINT" TP_25MIL-SMT 903.9,770 r270 top
TP8 "TESTPOINT" TP_25MIL-SMT 948.65,1245.24 r90 top
TP9 "TESTPOINT" TP_25MIL-SMT 948.65,1288.54 r90 top
TP10 "TESTPOINT" TP_25MIL-SMT 955.9,769 r270 top
TP11 "TESTPOINT" TP_25MIL-SMT 1008.9,769 r270 top
TP12 "TESTPOINT" TP_25MIL-SMT 1075.19,864.22 r90 top
TP13 "TESTPOINT" TP_25MIL-SMT 1079.12,824.22 r0 top
TP14 "TESTPOINT" TP_25MIL-SMT 2583.32,288.64 r180 top
TP15 "TESTPOINT" TP_25MIL-SMT 3038.48,595.4 r90 top
TP16 "TESTPOINT" TP_25MIL-SMT 3158.47,612.53 r0 top
TP17 "TP_SM_1MM" TP_SM_1MM 3166.98,1025.48 r90 top
TP18 "TP_SM_1MM" TP_SM_1MM 3170.86,1187.9 r90 top
TP19 "TESTPOINT" TP_25MIL-SMT 3171.17,184.71 r0 top
TP20 "TP_SM_1MM" TP_SM_1MM 3196.34,808.32 r90 top
TP21 "TP_SM_1MM" TP_SM_1MM 3250,808.32 r90 top
TP22 "TP_SM_1MM" TP_SM_1MM 3306.83,808.32 r90 top
TP23 "TP_SM_1MM" TP_SM_1MM 3363.67,808.32 r90 top
TP24 "TP_SM_1MM" TP_SM_1MM 3418.47,808.32 r90 top
TP25 "TESTPOINT" TP_25MIL-SMT 3432.6,628.57 r90 top
TP26 "TP_SM_1MM" TP_SM_1MM 3520.49,1315.72 r90 top
TP27 "TESTPOINT" TP_25MIL-SMT 3533.84,147.18 r0 top
TP28 "TP_SM_1MM" TP_SM_1MM 3563.91,988.08 r90 top
TP29 "TP_SM_1MM" TP_SM_1MM 3589.89,1105.45 r90 top
TP30 "TP_SM_1MM" TP_SM_1MM 3592.79,1155.27 r90 top
TP31 "TESTPOINT" TP_25MIL-SMT 3607.79,504.1 r270 top
TP32 "TP_SM_1MM" TP_SM_1MM 3633.29,1067.29 r90 top
TP33 "TP_SM_1MM" TP_SM_1MM 5717.64,732.72 r90 top
TP34 "TP_SM_1MM" TP_SM_1MM 5722.55,844.01 r90 top
TP35 "TP_SM_1MM" TP_SM_1MM 5723.41,790.88 r90 top
TP36 "TP_SM_1MM" TP_SM_1MM 5731.56,917.99 r90 top
TP37 "TP_SM_1MM" TP_SM_1MM 5731.56,968.63 r90 top
TP38 "TP_SM_1MM" TP_SM_1MM 5732.87,1016.46 r90 top
TP39 "TP_SM_1MM" TP_SM_1MM 6003.63,1145.32 r90 top
TP40 "TP_SM_1MM" TP_SM_1MM 6027.61,682.4 r90 top
TP41 "TP_SM_1MM" TP_SM_1MM 6050.85,744.69 r90 top
TP42 "TP_SM_1MM" TP_SM_1MM 6058.96,1145.32 r90 top
TP43 "TP_SM_1MM" TP_SM_1MM 6203.88,963.3 r90 top
TP44 "TP_SM_1MM" TP_SM_1MM 6235.8,826.4 r90 top
TP45 "TESTPOINT" TP_25MIL-SMT 6357.03,154.49 r180 top
TP46 "TESTPOINT" TP_25MIL-SMT 6547.36,2089.1 r0 top
TP47 "TESTPOINT" TP_25MIL-SMT 6553.85,225.77 r90 top
TP48 "TESTPOINT" TP_25MIL-SMT 6597.41,1830.42 r180 top
TP49 "TESTPOINT" TP_25MIL-SMT 6624.15,1849.55 r90 top
TP50 "TESTPOINT" TP_25MIL-SMT 6644.15,185.3 r90 top
TP51 "TESTPOINT" TP_25MIL-SMT 6675.2,172.83 r90 top
TP52 "TESTPOINT" TP_25MIL-SMT 6719.77,-70 r0 top
TP53 "TESTPOINT" TP_25MIL-SMT 6719.86,1759.06 r90 top
TP54 "TESTPOINT" TP_25MIL-SMT 6902.41,1854.87 r0 top
TP55 "TESTPOINT" TP_25MIL-SMT 6927.68,76.3 r90 top
TP56 "TESTPOINT" TP_25MIL-SMT 6965.83,2022.62 r0 top
TP57 "TESTPOINT" TP_25MIL-SMT 863.64,1834.23 r0 bottom
U1 "TPD4E02B04DQAR" DQA0010A#1 105,1088.92 r180 top
U2 "LM4040C25QDBZR" DBZ0003A_N 191.5,1284.76 r270 top
U3 "ISO7721DR" D0008B_HV 239.01,1740.81 r270 top locked
U4 "TPS79601DRBR" DRB0008B 318.69,848.32 r90 top
U5 "ISO1641BDR" D0008A-MFG 566.82,1740.81 r90 top locked
U6 "TUSB320LIRWBR" RWB0012A 685.56,220.68 r0 top
U7 "ISO7220CDR" D0008B_N 852.09,1740.81 r90 top locked
U8 "SN74AHC1G02DRLR" DRL0005A 940.66,240.6 r90 top
U9 "ISO6760DWR" DW0016A-MFG 1301.72,1512.95 r0 top locked
U10 "SN74LVC1G08DBVR" DBV0005A_N 1123.03,330.98 r90 top
U11 "ISO7220CDR" D0008B_N 1300,968.59 r0 top locked
U12 "ISO1641BDR" D0008A-MFG 1300,758.03 r180 top locked
U13 "ISO7721DR" D0008B_HV 1300,1194.73 r180 top locked
U14 "TPS22965TDSGRQ1" DSG0008B 1616.72,393.68 r0 top
U15 "SN74LVC1G17DCKR" DCK0005A_N 1732.95,1372.52 r90 top
U16 "TCA6408ARGTR" RGT0016A 1809.13,1039.54 r180 top
U17 "TPD4E02B04DQAR" DQA0010A#1 1806.54,273.34 r90 top
U18 "SN74LVC1G08DBVR" DBV0005A_N 1891.97,1399.88 r0 top
U19 "TPD4E02B04DQAR" DQA0010A#1 2069.81,283.89 r90 top
U20 "TLV75801PDRVR" DRV0006A 2134.1,510.44 r180 top
U21 "TPIC2810D" D0016A_N 2386.84,1482.42 r180 top locked
U22 "TPS2051BDBVR" DBV0005A_N 2449.33,404.94 r180 top
U23 "TCA6408ARGTR" RGT0016A 2498.69,722.15 r0 top
U24 "TPD4E02B04DQAR" DQA0010A#1 2674,159.39 r90 top
U25 "TXB0108RGYR" RGY0020A 2998.97,1549.07 r90 top
U26 "IS25WX064-JHLE" FP-IS25WX064-JHLE_TFBGA24-IPC_C 3333.26,1064.6 r0 top locked
U27 "SN74AHC1G09DBVR" DBV0005A_N 3319.48,1301.34 r0 top
U28 "TPS65036601RAYRQ1" RAY0024B-MFG 3355.95,381.54 r270 top locked
U29 "TXB0108RGYR" RGY0020A 3484.65,1553.2 r90 top
U30 "TLV7021DCKR" DCK0005A_N 3667.36,689.8 r0 top
U31 "TS3DDR3812RUAR" RUA0042A-MFG 3816.08,1602.98 r0 top
U32 "SN74CB3Q3253RGYR" RGY0016A 4012.8,434.49 r0 top
U33 "TPD4E02B04DQAR" DQA0010A#1 4085.92,281.34 r90 top
U34 "XAM2612AOFFHIZFB" Sitara_AM261_ZFG0304A 4337.6,1054.49 r0 top locked
U35 "TS5A23159DGSR" DGS0010A_N 4329.98,1651.01 r180 top
U36 "TPD4E02B04DQAR" DQA0010A#1 4369.09,281.34 r270 top
U37 "TS5A23159DGSR" DGS0010A_N 4641.87,1691.08 r0 top
U38 "TPD4E02B04DQAR" DQA0010A#1 4700.31,281.34 r270 top
U39 "SN74LVC1G08DBVR" DBV0005A_N 4914.43,1577.64 r180 top
U40 "SN74AHC1G86DBVR" DBV0005A_N 5065.82,1560.08 r270 top
U41 "TS5A23159DGSR" DGS0010A_N 5105.92,1846.61 r90 top
U42 "TCA6408ARGTR" RGT0016A 5208.52,1386.21 r180 top
U43 "SN74CB3Q3257PWR" PW0016A_L 5804.45,1249.5 r0 top
U44 "CAT24M01WI-GT3" SOIC-8 6178.45,1649.05 r0 top
U45 "SN74LVC1G08DBVR" DBV0005A_N 6388.87,338.19 r0 top
U46 "TS5A23159DGSR" DGS0010A_N 6806.78,1422.22 r180 top
U47 "SN74LVC1G08DBVR" DBV0005A_N 6864.73,1666.35 r180 top
U48 "TS5A23159DGSR" DGS0010A_N 7111.74,402.52 r0 top
U49 "TXS0101DCKR" DCK0006A_N 7200.68,659.58 r90 top
U50 "SN74AHC1G09DBVR" DBV0005A_N 6145.52,1240.64 r90 bottom locked
U51 "MX25UW6445GXDQ00" FP-MX25UW6445GXDQ00_BGA24-IPC_C 6043,884.34 r90 bottom
U52 "TCAN1044VDRBTQ1" DRB0008J 6113.11,257.71 r180 bottom
U53 "TXB0108RGYR" RGY0020A 5445.49,1241.4 r90 bottom
U54 "TS3DDR3812RUAR" RUA0042A-MFG 5328.08,836.03 r0 bottom
U55 "SN74LVC1G14DCKT" DCK0005A_N 4918.17,1574.72 r270 bottom
U56 "SN74CB3Q3257RGYR" RGY0016A-MFG 3767.91,122.41 r270 bottom
U57 "SN74CB3Q3257RGYR" RGY0016A-MFG 3765.05,415.63 r270 bottom
U58 "TLV7021DCKR" DCK0005A_N 2895.63,560.62 r90 bottom
U59 "TS3USBA225RUTR" RUT0012A 2643.82,556.52 r90 bottom
U60 "SN74LVC1G08DBVR" DBV0005A_N 2332.6,1267.1 r0 bottom
U61 "SN74AVC4T245RSVR" RSV0016A 2257,1005.15 r90 bottom
U62 "SN74LVC1G07DCKT" DCK0005A_N 1005,1905.04 r270 bottom
U63 "TM4C1294NCPDTT3" PDT0128A 645.5,1174.37 r0 bottom locked
U64 "SN74LVC2G17DSF2" DSF0006A 535.43,2030.2 r0 bottom
U65 "TPD4E02B04DQAR" DQA0010A#2 322.45,497.27 r0 bottom
Y1 "ABM10W-25.0000MHZ-4-D1X-T3" Abracon_ABM10W 3967.32,648.05 r270 top
Y2 "ASCO-25.000MHZ-EK-T3" FP-ASCO-25.000MHZ-EK-T3_SMT4_1MM6_1MM2-MFG 6635.1,354.29 r270 top
Y3 "ASCO-25.000MHZ-EK-T3" FP-ASCO-25.000MHZ-EK-T3_SMT4_1MM6_1MM2-MFG 6626.4,1653.21 r90 top
Y4 "NX3225GA-16.000M-STD-CRG-1" NDK_NX3225GA 1137.13,1054.32 r180 bottom locked
ZZ1 "These assemblies must comply with workmanship standards IPC-A-610 Class 2, unless otherwise specified." AssemblyNote -10,5210 r0 top
ZZ2 "These assemblies must be clean and free from flux and all contaminants. Use of no clean flux is not acceptable." AssemblyNote -10,5310 r0 top
ZZ3 "These assemblies are ESD sensitive, ESD precautions shall be observed." AssemblyNote -10,5410 r0 top
ZZ4 "This Assembly Note is for PCB labels only" AssemblyNoteLabel -10,5510 r0 top

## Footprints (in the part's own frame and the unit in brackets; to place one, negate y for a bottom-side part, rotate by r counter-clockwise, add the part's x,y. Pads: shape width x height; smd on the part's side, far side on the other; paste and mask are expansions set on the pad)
0201 [mm] "Data from Kemet datasheet CC101_COM dated 7/28/11"
  rect 0.46x0.42 smd mask+0.048: 1(-0.33,0) 2(0.33,0)
  body extent -0.31,-0.16 0.31,0.16, height 0.26
0402 [mm] "0402 from SM-752 data"
  rect 0.8x0.6 smd: 1(-0.6,0) 2(0.6,0)
  silkscreen extent -1.22,-0.52 1.22,0.52, body extent -0.55,-0.3 0.55,0.3, height 0.6
0402_070 [mil] "SMD, 2-Leads, Body 1.2x0.7mm, Height 0.7mm"
  rect 15x24 smd: 1(-20,0) 2(20,0)
  body extent -24,-14 24,14, height 28
0402L [mm] "0402 from SM-752 data"
  rect 0.6x0.5 smd: 1(-0.5,0) 2(0.5,0)
  body extent -0.55,-0.3 0.55,0.3, height 0.6
0402S [mil] "Based on C0402S footprint from PADS legacy"
  rect 15x24 smd: 1(-20,0) 2(20,0)
  body extent -22,-12 22,12, height 24
0603 [mm] "0603 from SM-752 data"
  rect 1x0.95 smd: 1(-0.8,0) 2(0.8,0)
  silkscreen extent -1.52,-0.69 1.52,0.69, body extent -0.87,-0.47 0.87,0.47, height 1
0805_HV [mil] "0805 with 30mil clearance between pads"
  rect 50x63 smd: 1(-40,0) 2(40,0)
  silkscreen extent -74,-40 74,40, body extent -43,-29 43,29, height 57
0805L [mm] "0805 from SM-752 data"
  rect 1.1x1.4 smd: 1(-0.75,0) 2(0.75,0)
  body extent -1.1,-0.72 1.1,0.72, height 1.45
1210_270 [mm] "1210"
  rect 1.3x2.7 smd: 1(-1.45,0) 2(1.45,0)
  silkscreen extent -2.32,-1.57 2.32,1.57, body extent -1.7,-1.35 1.7,1.35, height 2.7
1808 [mm] "Chip Capacitor, Body 4.6x2.0mm, IPC Medium Density"
  rect 1.4x2.3 smd: 1(-2.1,0) 2(2.1,0)
  silkscreen extent -3.1,-1.45 3.1,1.45, body extent -2.47,-1.2 2.47,1.2, height 2.03
Abracon_ABM10W [mm] "SMD, 4-Leads, Body 2x2.5mm"
  rrect12% 0.85x1.2 smd: 1(-0.6,0.813) 2(-0.6,-0.813) 3(0.6,-0.813) 4(0.6,0.813)
  body extent -1.05,-1.3 1.05,1.3, height 0.6
AssemblyNote [mil] "Assembly Note"
AssemblyNoteLabel [mil] "Assembly Note for PCB Labels"
BOOSTERPACK_40PIN_J1J3 [mm] "Receptacle, 2.54mm, 10x2, TH"
  rrect6% 1.55x1.55 hole 1.02: 1(1.27,11.43)
  round 1.55 hole 1.02: 2(1.27,8.89) 3(1.27,6.35) 4(1.27,3.81) 5(1.27,1.27) 6(1.27,-1.27) 7(1.27,-3.81) 8(1.27,-6.35) 9(1.27,-8.89) 10(1.27,-11.43) 21(-1.27,11.43) 22(-1.27,8.89) 23(-1.27,6.35) 24(-1.27,3.81) 25(-1.27,1.27) 26(-1.27,-1.27) 27(-1.27,-3.81) 28(-1.27,-6.35) 29(-1.27,-8.89) 30(-1.27,-11.43)
  silkscreen extent -2.48,-12.95 2.48,12.95, body extent -2.48,-12.95 2.48,12.95, height 8.51
BoosterPack_40pin_J2J4 [mm] "Receptacle, 2.54mm, 10x2, TH"
  round 1.55 hole 1.02: 11(-1.27,-11.43) 12(-1.27,-8.89) 13(-1.27,-6.35) 14(-1.27,-3.81) 15(-1.27,-1.27) 16(-1.27,1.27) 17(-1.27,3.81) 18(-1.27,6.35) 19(-1.27,8.89) 20(-1.27,11.43) 31(1.27,-11.43) 32(1.27,-8.89) 33(1.27,-6.35) 34(1.27,-3.81) 35(1.27,-1.27) 36(1.27,1.27) 37(1.27,3.81) 38(1.27,6.35) 39(1.27,8.89) 40(1.27,11.43)
  silkscreen extent -7.62,-12.95 2.48,12.95, body extent -2.48,-12.95 2.48,12.95, height 8.51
